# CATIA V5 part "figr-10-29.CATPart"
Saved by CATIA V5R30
Part number: Part1
Bounding box of the stored display mesh (mm): x -60 to 70, y 0 to 100.393, z 0 to 0
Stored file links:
  D:\PROJECTS\CATIA V56R 2020\Resources\Parts File\c10_catia_v5_6r2020_prt\figr-10-29.CATPart
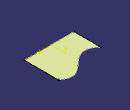
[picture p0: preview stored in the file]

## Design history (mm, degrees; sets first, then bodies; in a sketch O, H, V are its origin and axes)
Set1
  Sweep1: type Segment, GuideCrv (Sketch1; Sketch2), Length1 0, Length2 0
Body1 (main body)
  Sketch1 on xy-plane, origin (0, 0, 0), H (1, 0, 0), V (0, 1, 0)
    line L1 (-60, 0) -> (70, 0)
    point P1 (-60, 0)
    coincidence: P1 H
    horizontal: L1 H
  Sketch2 on xy-plane, origin (0, 0, 0), H (1, 0, 0), V (0, 1, 0)
    spline S1 through (-60, 70) (-20, 60) (40, 100) (70, 90)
